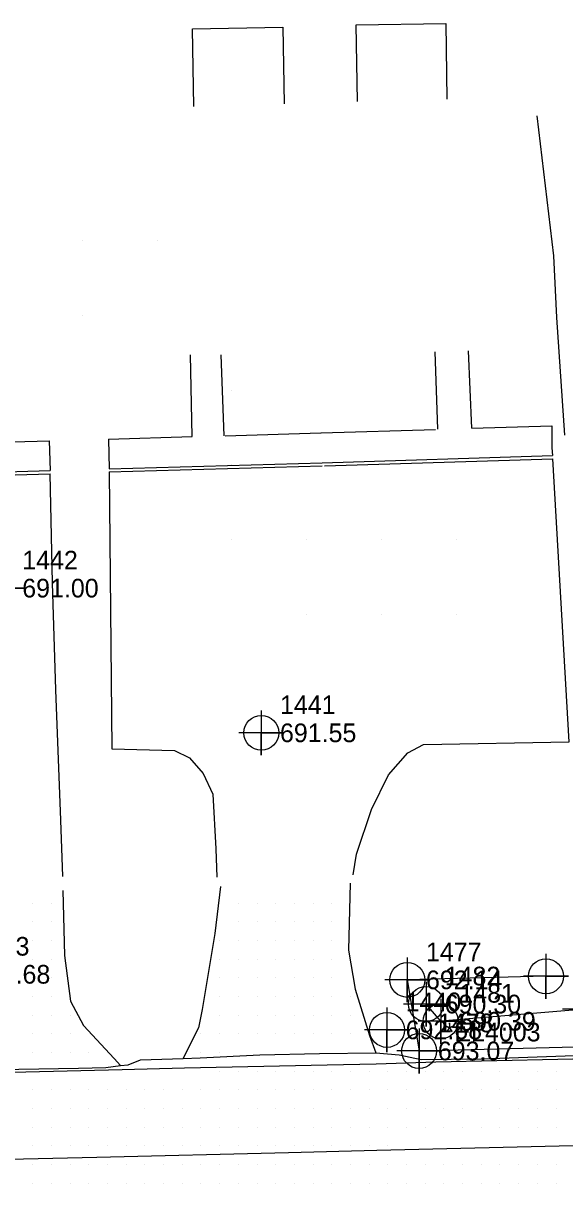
# Model space of a CAD drawing. Extents: x 1755643 to 1760494, y 736519 to 737621.
# Drawn here: x 1758017.5 to 1758089.9, y 736988 to 737144.1 of the extents above; entities that cross this region are included whole.
import ezdxf

# ---------------------------------------------------------------- set-up
doc = ezdxf.new("R2010")
doc.units = 0
for name, color, linetype in [('Exist Horizontal Alignment Curve and Spiral Data', 7, 'Continuous'), ('Exist Railroads Standard Gauge', 7, 'Continuous'), ('Exist Roads EOT', 7, 'Continuous'), ('Old_Level_1', 7, 'Continuous'), ('Old_Level_10', 7, 'Continuous'), ('Old_Level_2', 7, 'Continuous'), ('Old_Level_3', 7, 'Continuous'), ('Prop Corridor Linear Feature', 7, 'Continuous'), ('Prop Dimension', 7, 'Continuous'), ('Prop EOT Dash', 7, 'Continuous'), ('Prop Horizontal Alignment Direction Label', 7, 'Continuous'), ('Prop Lane Lines', 7, 'Continuous'), ('Prop Paint Stripe', 7, 'Continuous'), ('Prop Paved Shoulder', 7, 'Continuous'), ('Scratch_Level_1', 7, 'Continuous'), ('Scratch_Level_2', 7, 'Continuous'), ('Scratch_Level_5', 7, 'Continuous'), ('Scratch_Level_6', 7, 'Continuous'), ('Scratch_Level_9', 7, 'Continuous')]:
    doc.layers.add(name, color=color, linetype=linetype)

msp = doc.modelspace()

# ---------------------------------------------------------------- linework, layer by layer
at = {"layer": 'Exist Horizontal Alignment Curve and Spiral Data'}
for points in [[(1758014.84, 737071.46), (1758014.84, 737065.46), (1758014.84, 737068.46), (1758017.84, 737068.46), (1758011.84, 737068.46)], [(1758049.32, 737052.08), (1758049.32, 737046.08), (1758049.32, 737049.08), (1758052.32, 737049.08), (1758046.32, 737049.08)], [(1758066.13, 737012.29), (1758066.13, 737006.29), (1758066.13, 737009.29), (1758069.13, 737009.29), (1758063.13, 737009.29)]]:
    msp.add_lwpolyline(points, dxfattribs=at)
for centre in [(1758049.32, 737049.08), (1758066.13, 737009.29)]:
    msp.add_circle(centre, 2.34, dxfattribs=at)
at = {"layer": 'Exist Railroads Standard Gauge'}
for p, q in [((1758040.06, 737088.75), (1758039.84, 737099.72)), ((1758043.91, 737099.7), (1758044.31, 737088.88)), ((1758072.95, 737089.74), (1758072.58, 737100.1)), ((1758077.51, 737089.88), (1758077.05, 737100.23)), ((1758057.33, 737089.25), (1758072.61, 737089.73)), ((1758077.51, 737089.88), (1758088.17, 737090.22)), ((1758020.95, 737088.2), (1758021.07, 737084.2)), ((1758028.87, 737088.43), (1758040.06, 737088.75)), ((1758028.87, 737088.43), (1758028.98, 737084.43)), ((1758044.49, 737088.88), (1758057.29, 737089.25)), ((1758028.98, 737084.43), (1758057.46, 737085.25)), ((1758028.99, 737084.02), (1758057.47, 737084.84)), ((1758057.46, 737085.25), (1758088.3, 737086.22)), ((1758057.77, 737084.84), (1758088.31, 737085.8)), ((1758021.41, 737069.17), (1758021.08, 737083.78))]:
    msp.add_line(p, q, dxfattribs=at)
for points in [[(1758062.21, 737133.62), (1758062.03, 737143.91), (1758073.99, 737144.11), (1758074.16, 737133.97)], [(1758040.3, 737132.98), (1758040.12, 737143.36), (1758052.2, 737143.58), (1758052.38, 737133.34)], [(1758086.17, 737131.72), (1758088.43, 737112.98), (1758088.8, 737104.7), (1758089.87, 737088.96)], [(1758088.17, 737090.22), (1758088.2, 737087.24), (1758088.2, 737087.24), (1758088.3, 737086.22)], [(1758009.58, 737087.86), (1758020.95, 737088.2)], [(1758061.63, 737030.06), (1758062.06, 737032.81), (1758064.05, 737038.81), (1758066.35, 737043.44), (1758068.93, 737046.42), (1758071.04, 737047.5), (1758090.51, 737047.87), (1758088.31, 737085.8)], [(1757961.38, 737082.36), (1757991.35, 737083.32), (1758021.07, 737084.2)], [(1757961.39, 737081.94), (1757991.37, 737082.91), (1758021.08, 737083.78)], [(1758028.99, 737084.02), (1758029.34, 737046.94), (1758037.73, 737046.73), (1758039.7, 737045.75), (1758041.55, 737043.64), (1758042.86, 737040.88), (1758043.26, 737033.56), (1758043.36, 737029.73)], [(1758022.78, 737029.85), (1758022.49, 737037.37), (1758021.83, 737054.85), (1758021.41, 737069.17)]]:
    msp.add_lwpolyline(points, dxfattribs=at)
at = {"layer": 'Old_Level_10'}
for points in [[(1758071.36, 737015.75), (1758071.36, 737009.75), (1758071.36, 737012.75), (1758074.36, 737012.75), (1758068.36, 737012.75)], [(1758092.6, 737015.06), (1758092.6, 737009.06), (1758092.6, 737012.06), (1758095.6, 737012.06), (1758089.6, 737012.06)], [(1758073.32, 737013.44), (1758073.32, 737007.44), (1758073.32, 737010.44), (1758076.32, 737010.44), (1758070.32, 737010.44)]]:
    msp.add_lwpolyline(points, dxfattribs=at)
for centre in [(1758071.36, 737012.75), (1758073.32, 737010.44)]:
    msp.add_circle(centre, 2.34, dxfattribs=at)
at = {"layer": 'Prop Corridor Linear Feature'}
for points in [[(1758038.86, 737005.48), (1758041.15, 737005.55), (1758049.14, 737005.94), (1758057.13, 737006.15), (1758064.64, 737006.23)], [(1758000.88, 737003.6), (1758008.88, 737003.81), (1758016.87, 737004.02), (1758024.87, 737004.15), (1758028.53, 737004.27), (1758030.5, 737004.51)]]:
    msp.add_lwpolyline(points, dxfattribs=at)
at = {"layer": 'Prop Dimension'}
msp.add_lwpolyline([(1758092.6, 737012.06), (1758073.32, 737010.44), (1758071.36, 737012.75)], dxfattribs=at)
at = {"layer": 'Prop Lane Lines'}
for points in [[(1758087.4, 737019.47), (1758087.4, 737013.47), (1758087.4, 737016.47), (1758090.4, 737016.47), (1758084.4, 737016.47)], [(1758068.85, 737018.99), (1758068.85, 737012.99), (1758068.85, 737015.99), (1758071.85, 737015.99), (1758065.85, 737015.99)], [(1758070.44, 737009.47), (1758070.44, 737003.47), (1758070.44, 737006.47), (1758073.44, 737006.47), (1758067.44, 737006.47)]]:
    msp.add_lwpolyline(points, dxfattribs=at)
for centre in [(1758068.85, 737015.99), (1758087.4, 737016.47), (1758070.44, 737006.47)]:
    msp.add_circle(centre, 2.34, dxfattribs=at)
at = {"layer": 'Prop Paint Stripe'}
for p, q in [((1758025.4, 737115), (1758025.4, 737115)), ((1758035.4, 737115), (1758035.4, 737115)), ((1758025.4, 737105), (1758025.4, 737105)), ((1758045.4, 737094.99), (1758045.4, 737094.99)), ((1758045.4, 737084.99), (1758045.4, 737084.99)), ((1758045.4, 737074.99), (1758045.4, 737074.99)), ((1758055.4, 737074.99), (1758055.4, 737074.99)), ((1758065.4, 737074.99), (1758065.4, 737074.99)), ((1758075.4, 737074.99), (1758075.4, 737074.99)), ((1758055.4, 737064.99), (1758055.4, 737064.99)), ((1758065.4, 737064.99), (1758065.4, 737064.99)), ((1758075.4, 737064.99), (1758075.4, 737064.99))]:
    msp.add_line(p, q, dxfattribs=at)
at = {"layer": 'Scratch_Level_1'}
for points in [[(1758064.64, 737006.23), (1758067.75, 737005.95), (1758070.73, 737005.31), (1758078.73, 737005.43), (1758093.71, 737005.95), (1758108.69, 737006.38), (1758123.68, 737006.69), (1758138.67, 737007.07), (1758153.65, 737007.78), (1758168.64, 737008.2), (1758183.63, 737008.63), (1758188.93, 737008.88)], [(1758030.5, 737004.51), (1758031.53, 737004.63), (1758033.15, 737005.3), (1758038.86, 737005.48)]]:
    msp.add_lwpolyline(points, dxfattribs=at)
at = {"layer": 'Scratch_Level_2'}
for p, q in [((1758018.75, 737026.25), (1758018.75, 737026.25)), ((1758021.25, 737026.25), (1758021.25, 737026.25)), ((1758046.25, 737026.25), (1758046.25, 737026.25)), ((1758048.75, 737026.25), (1758048.75, 737026.25)), ((1758051.25, 737026.25), (1758051.25, 737026.25)), ((1758053.75, 737026.25), (1758053.75, 737026.25)), ((1758056.25, 737026.25), (1758056.25, 737026.25)), ((1758058.75, 737026.25), (1758058.75, 737026.25)), ((1758018.75, 737023.75), (1758018.75, 737023.75)), ((1758021.25, 737023.75), (1758021.25, 737023.75)), ((1758046.25, 737023.75), (1758046.25, 737023.75)), ((1758048.75, 737023.75), (1758048.75, 737023.75)), ((1758051.25, 737023.75), (1758051.25, 737023.75)), ((1758053.75, 737023.75), (1758053.75, 737023.75)), ((1758056.25, 737023.75), (1758056.25, 737023.75)), ((1758058.75, 737023.75), (1758058.75, 737023.75)), ((1758018.75, 737021.25), (1758018.75, 737021.25)), ((1758021.25, 737021.25), (1758021.25, 737021.25)), ((1758043.75, 737021.25), (1758043.75, 737021.25)), ((1758046.25, 737021.25), (1758046.25, 737021.25)), ((1758048.75, 737021.25), (1758048.75, 737021.25)), ((1758051.25, 737021.25), (1758051.25, 737021.25)), ((1758053.75, 737021.25), (1758053.75, 737021.25)), ((1758056.25, 737021.25), (1758056.25, 737021.25)), ((1758058.75, 737021.25), (1758058.75, 737021.25)), ((1758018.75, 737018.75), (1758018.75, 737018.75)), ((1758021.25, 737018.75), (1758021.25, 737018.75)), ((1758043.75, 737018.75), (1758043.75, 737018.75)), ((1758046.25, 737018.75), (1758046.25, 737018.75)), ((1758048.75, 737018.75), (1758048.75, 737018.75)), ((1758051.25, 737018.75), (1758051.25, 737018.75)), ((1758053.75, 737018.75), (1758053.75, 737018.75)), ((1758056.25, 737018.75), (1758056.25, 737018.75)), ((1758058.75, 737018.75), (1758058.75, 737018.75)), ((1758018.75, 737016.25), (1758018.75, 737016.25)), ((1758021.25, 737016.25), (1758021.25, 737016.25)), ((1758043.75, 737016.25), (1758043.75, 737016.25)), ((1758046.25, 737016.25), (1758046.25, 737016.25)), ((1758048.75, 737016.25), (1758048.75, 737016.25)), ((1758051.25, 737016.25), (1758051.25, 737016.25)), ((1758053.75, 737016.25), (1758053.75, 737016.25)), ((1758056.25, 737016.25), (1758056.25, 737016.25)), ((1758058.75, 737016.25), (1758058.75, 737016.25)), ((1758018.75, 737013.75), (1758018.75, 737013.75)), ((1758021.25, 737013.75), (1758021.25, 737013.75)), ((1758043.75, 737013.75), (1758043.75, 737013.75)), ((1758046.25, 737013.75), (1758046.25, 737013.75)), ((1758048.75, 737013.75), (1758048.75, 737013.75)), ((1758051.25, 737013.75), (1758051.25, 737013.75)), ((1758053.75, 737013.75), (1758053.75, 737013.75)), ((1758056.25, 737013.75), (1758056.25, 737013.75)), ((1758058.75, 737013.75), (1758058.75, 737013.75)), ((1758061.25, 737013.75), (1758061.25, 737013.75)), ((1758018.75, 737011.25), (1758018.75, 737011.25)), ((1758021.25, 737011.25), (1758021.25, 737011.25)), ((1758023.75, 737011.25), (1758023.75, 737011.25)), ((1758043.75, 737011.25), (1758043.75, 737011.25)), ((1758046.25, 737011.25), (1758046.25, 737011.25)), ((1758048.75, 737011.25), (1758048.75, 737011.25)), ((1758051.25, 737011.25), (1758051.25, 737011.25)), ((1758053.75, 737011.25), (1758053.75, 737011.25)), ((1758056.25, 737011.25), (1758056.25, 737011.25)), ((1758058.75, 737011.25), (1758058.75, 737011.25)), ((1758061.25, 737011.25), (1758061.25, 737011.25)), ((1758018.75, 737008.75), (1758018.75, 737008.75)), ((1758021.25, 737008.75), (1758021.25, 737008.75)), ((1758023.75, 737008.75), (1758023.75, 737008.75)), ((1758041.25, 737008.75), (1758041.25, 737008.75)), ((1758043.75, 737008.75), (1758043.75, 737008.75)), ((1758046.25, 737008.75), (1758046.25, 737008.75)), ((1758048.75, 737008.75), (1758048.75, 737008.75)), ((1758051.25, 737008.75), (1758051.25, 737008.75)), ((1758053.75, 737008.75), (1758053.75, 737008.75)), ((1758056.25, 737008.75), (1758056.25, 737008.75)), ((1758058.75, 737008.75), (1758058.75, 737008.75)), ((1758061.25, 737008.75), (1758061.25, 737008.75)), ((1758018.75, 737006.25), (1758018.75, 737006.25)), ((1758021.25, 737006.25), (1758021.25, 737006.25)), ((1758023.75, 737006.25), (1758023.75, 737006.25)), ((1758026.25, 737006.25), (1758026.25, 737006.25)), ((1758041.25, 737006.25), (1758041.25, 737006.25)), ((1758043.75, 737006.25), (1758043.75, 737006.25)), ((1758043.75, 737003.75), (1758043.75, 737003.75)), ((1758046.25, 737003.75), (1758046.25, 737003.75)), ((1758048.75, 737003.75), (1758048.75, 737003.75)), ((1758051.25, 737003.75), (1758051.25, 737003.75)), ((1758053.75, 737003.75), (1758053.75, 737003.75)), ((1758056.25, 737003.75), (1758056.25, 737003.75)), ((1758058.75, 737003.75), (1758058.75, 737003.75)), ((1758061.25, 737003.75), (1758061.25, 737003.75)), ((1758063.75, 737003.75), (1758063.75, 737003.75)), ((1758066.25, 737003.75), (1758066.25, 737003.75)), ((1758068.75, 737003.75), (1758068.75, 737003.75)), ((1758071.25, 737003.75), (1758071.25, 737003.75)), ((1758073.75, 737003.75), (1758073.75, 737003.75)), ((1758076.25, 737003.75), (1758076.25, 737003.75)), ((1758078.75, 737003.75), (1758078.75, 737003.75)), ((1758081.25, 737003.75), (1758081.25, 737003.75)), ((1758083.75, 737003.75), (1758083.75, 737003.75)), ((1758086.25, 737003.75), (1758086.25, 737003.75)), ((1758088.75, 737003.75), (1758088.75, 737003.75)), ((1758018.75, 737001.25), (1758018.75, 737001.25)), ((1758021.25, 737001.25), (1758021.25, 737001.25)), ((1758023.75, 737001.25), (1758023.75, 737001.25)), ((1758026.25, 737001.25), (1758026.25, 737001.25)), ((1758028.75, 737001.25), (1758028.75, 737001.25)), ((1758031.25, 737001.25), (1758031.25, 737001.25)), ((1758033.75, 737001.25), (1758033.75, 737001.25)), ((1758036.25, 737001.25), (1758036.25, 737001.25)), ((1758038.75, 737001.25), (1758038.75, 737001.25)), ((1758041.25, 737001.25), (1758041.25, 737001.25)), ((1758043.75, 737001.25), (1758043.75, 737001.25)), ((1758046.25, 737001.25), (1758046.25, 737001.25)), ((1758048.75, 737001.25), (1758048.75, 737001.25)), ((1758051.25, 737001.25), (1758051.25, 737001.25)), ((1758053.75, 737001.25), (1758053.75, 737001.25)), ((1758056.25, 737001.25), (1758056.25, 737001.25)), ((1758058.75, 737001.25), (1758058.75, 737001.25)), ((1758061.25, 737001.25), (1758061.25, 737001.25)), ((1758063.75, 737001.25), (1758063.75, 737001.25)), ((1758066.25, 737001.25), (1758066.25, 737001.25)), ((1758068.75, 737001.25), (1758068.75, 737001.25)), ((1758071.25, 737001.25), (1758071.25, 737001.25)), ((1758073.75, 737001.25), (1758073.75, 737001.25)), ((1758076.25, 737001.25), (1758076.25, 737001.25)), ((1758078.75, 737001.25), (1758078.75, 737001.25)), ((1758081.25, 737001.25), (1758081.25, 737001.25)), ((1758083.75, 737001.25), (1758083.75, 737001.25)), ((1758086.25, 737001.25), (1758086.25, 737001.25)), ((1758088.75, 737001.25), (1758088.75, 737001.25)), ((1758018.75, 736998.75), (1758018.75, 736998.75)), ((1758021.25, 736998.75), (1758021.25, 736998.75)), ((1758023.75, 736998.75), (1758023.75, 736998.75)), ((1758026.25, 736998.75), (1758026.25, 736998.75)), ((1758028.75, 736998.75), (1758028.75, 736998.75)), ((1758031.25, 736998.75), (1758031.25, 736998.75)), ((1758033.75, 736998.75), (1758033.75, 736998.75)), ((1758036.25, 736998.75), (1758036.25, 736998.75)), ((1758038.75, 736998.75), (1758038.75, 736998.75)), ((1758041.25, 736998.75), (1758041.25, 736998.75)), ((1758043.75, 736998.75), (1758043.75, 736998.75)), ((1758046.25, 736998.75), (1758046.25, 736998.75)), ((1758048.75, 736998.75), (1758048.75, 736998.75)), ((1758051.25, 736998.75), (1758051.25, 736998.75)), ((1758053.75, 736998.75), (1758053.75, 736998.75)), ((1758056.25, 736998.75), (1758056.25, 736998.75)), ((1758058.75, 736998.75), (1758058.75, 736998.75)), ((1758061.25, 736998.75), (1758061.25, 736998.75)), ((1758063.75, 736998.75), (1758063.75, 736998.75)), ((1758066.25, 736998.75), (1758066.25, 736998.75)), ((1758068.75, 736998.75), (1758068.75, 736998.75)), ((1758071.25, 736998.75), (1758071.25, 736998.75)), ((1758073.75, 736998.75), (1758073.75, 736998.75)), ((1758076.25, 736998.75), (1758076.25, 736998.75)), ((1758078.75, 736998.75), (1758078.75, 736998.75)), ((1758081.25, 736998.75), (1758081.25, 736998.75)), ((1758083.75, 736998.75), (1758083.75, 736998.75)), ((1758086.25, 736998.75), (1758086.25, 736998.75)), ((1758088.75, 736998.75), (1758088.75, 736998.75)), ((1758018.75, 736996.25), (1758018.75, 736996.25)), ((1758021.25, 736996.25), (1758021.25, 736996.25)), ((1758023.75, 736996.25), (1758023.75, 736996.25)), ((1758026.25, 736996.25), (1758026.25, 736996.25)), ((1758028.75, 736996.25), (1758028.75, 736996.25)), ((1758031.25, 736996.25), (1758031.25, 736996.25)), ((1758033.75, 736996.25), (1758033.75, 736996.25)), ((1758036.25, 736996.25), (1758036.25, 736996.25)), ((1758038.75, 736996.25), (1758038.75, 736996.25)), ((1758041.25, 736996.25), (1758041.25, 736996.25)), ((1758043.75, 736996.25), (1758043.75, 736996.25)), ((1758046.25, 736996.25), (1758046.25, 736996.25)), ((1758048.75, 736996.25), (1758048.75, 736996.25)), ((1758051.25, 736996.25), (1758051.25, 736996.25)), ((1758053.75, 736996.25), (1758053.75, 736996.25)), ((1758056.25, 736996.25), (1758056.25, 736996.25)), ((1758058.75, 736996.25), (1758058.75, 736996.25)), ((1758061.25, 736996.25), (1758061.25, 736996.25)), ((1758063.75, 736996.25), (1758063.75, 736996.25)), ((1758066.25, 736996.25), (1758066.25, 736996.25)), ((1758068.75, 736996.25), (1758068.75, 736996.25)), ((1758071.25, 736996.25), (1758071.25, 736996.25)), ((1758073.75, 736996.25), (1758073.75, 736996.25)), ((1758076.25, 736996.25), (1758076.25, 736996.25)), ((1758078.75, 736996.25), (1758078.75, 736996.25)), ((1758081.25, 736996.25), (1758081.25, 736996.25)), ((1758083.75, 736996.25), (1758083.75, 736996.25)), ((1758086.25, 736996.25), (1758086.25, 736996.25)), ((1758088.75, 736996.25), (1758088.75, 736996.25)), ((1758018.75, 736993.75), (1758018.75, 736993.75)), ((1758021.25, 736993.75), (1758021.25, 736993.75)), ((1758023.75, 736993.75), (1758023.75, 736993.75)), ((1758026.25, 736993.75), (1758026.25, 736993.75)), ((1758028.75, 736993.75), (1758028.75, 736993.75)), ((1758031.25, 736993.75), (1758031.25, 736993.75)), ((1758033.75, 736993.75), (1758033.75, 736993.75)), ((1758036.25, 736993.75), (1758036.25, 736993.75)), ((1758038.75, 736993.75), (1758038.75, 736993.75)), ((1758041.25, 736993.75), (1758041.25, 736993.75)), ((1758043.75, 736993.75), (1758043.75, 736993.75)), ((1758046.25, 736993.75), (1758046.25, 736993.75)), ((1758048.75, 736993.75), (1758048.75, 736993.75)), ((1758051.25, 736993.75), (1758051.25, 736993.75)), ((1758053.75, 736993.75), (1758053.75, 736993.75)), ((1758056.25, 736993.75), (1758056.25, 736993.75)), ((1758058.75, 736993.75), (1758058.75, 736993.75)), ((1758061.25, 736993.75), (1758061.25, 736993.75)), ((1758063.75, 736993.75), (1758063.75, 736993.75)), ((1758066.25, 736993.75), (1758066.25, 736993.75)), ((1758018.75, 736991.25), (1758018.75, 736991.25)), ((1758021.25, 736991.25), (1758021.25, 736991.25)), ((1758023.75, 736991.25), (1758023.75, 736991.25)), ((1758026.25, 736991.25), (1758026.25, 736991.25)), ((1758028.75, 736991.25), (1758028.75, 736991.25)), ((1758031.25, 736991.25), (1758031.25, 736991.25)), ((1758033.75, 736991.25), (1758033.75, 736991.25)), ((1758036.25, 736991.25), (1758036.25, 736991.25)), ((1758038.75, 736991.25), (1758038.75, 736991.25)), ((1758041.25, 736991.25), (1758041.25, 736991.25)), ((1758043.75, 736991.25), (1758043.75, 736991.25)), ((1758046.25, 736991.25), (1758046.25, 736991.25)), ((1758048.75, 736991.25), (1758048.75, 736991.25)), ((1758051.25, 736991.25), (1758051.25, 736991.25)), ((1758053.75, 736991.25), (1758053.75, 736991.25)), ((1758056.25, 736991.25), (1758056.25, 736991.25)), ((1758058.75, 736991.25), (1758058.75, 736991.25)), ((1758061.25, 736991.25), (1758061.25, 736991.25)), ((1758063.75, 736991.25), (1758063.75, 736991.25)), ((1758066.25, 736991.25), (1758066.25, 736991.25)), ((1758068.75, 736991.25), (1758068.75, 736991.25)), ((1758071.25, 736991.25), (1758071.25, 736991.25)), ((1758073.75, 736991.25), (1758073.75, 736991.25)), ((1758076.25, 736991.25), (1758076.25, 736991.25)), ((1758078.75, 736991.25), (1758078.75, 736991.25)), ((1758081.25, 736991.25), (1758081.25, 736991.25)), ((1758083.75, 736991.25), (1758083.75, 736991.25)), ((1758086.25, 736991.25), (1758086.25, 736991.25)), ((1758088.75, 736991.25), (1758088.75, 736991.25)), ((1758018.75, 736988.75), (1758018.75, 736988.75)), ((1758021.25, 736988.75), (1758021.25, 736988.75)), ((1758023.75, 736988.75), (1758023.75, 736988.75)), ((1758026.25, 736988.75), (1758026.25, 736988.75)), ((1758028.75, 736988.75), (1758028.75, 736988.75)), ((1758031.25, 736988.75), (1758031.25, 736988.75)), ((1758033.75, 736988.75), (1758033.75, 736988.75)), ((1758036.25, 736988.75), (1758036.25, 736988.75)), ((1758038.75, 736988.75), (1758038.75, 736988.75)), ((1758041.25, 736988.75), (1758041.25, 736988.75)), ((1758043.75, 736988.75), (1758043.75, 736988.75)), ((1758046.25, 736988.75), (1758046.25, 736988.75)), ((1758048.75, 736988.75), (1758048.75, 736988.75)), ((1758051.25, 736988.75), (1758051.25, 736988.75)), ((1758053.75, 736988.75), (1758053.75, 736988.75)), ((1758056.25, 736988.75), (1758056.25, 736988.75)), ((1758058.75, 736988.75), (1758058.75, 736988.75)), ((1758061.25, 736988.75), (1758061.25, 736988.75)), ((1758063.75, 736988.75), (1758063.75, 736988.75)), ((1758066.25, 736988.75), (1758066.25, 736988.75)), ((1758068.75, 736988.75), (1758068.75, 736988.75)), ((1758071.25, 736988.75), (1758071.25, 736988.75)), ((1758073.75, 736988.75), (1758073.75, 736988.75)), ((1758076.25, 736988.75), (1758076.25, 736988.75)), ((1758078.75, 736988.75), (1758078.75, 736988.75)), ((1758081.25, 736988.75), (1758081.25, 736988.75)), ((1758083.75, 736988.75), (1758083.75, 736988.75)), ((1758086.25, 736988.75), (1758086.25, 736988.75)), ((1758088.75, 736988.75), (1758088.75, 736988.75))]:
    msp.add_line(p, q, dxfattribs=at)
at = {"layer": 'Scratch_Level_5'}
for points in [[(1758064.69, 737004.75), (1758072.66, 737005.01), (1758089, 737005.36), (1758105.09, 737005.72), (1758122.29, 737006.14), (1758136.53, 737006.53), (1758157.9, 737007.11), (1758173.26, 737007.48), (1758191.67, 737007.95), (1758209.14, 737008.37), (1758232.19, 737008.9), (1758248.18, 737009.28), (1758264.32, 737009.73)], [(1757864.46, 736999.5), (1757881.5, 736999.9), (1757895.35, 737000.32), (1757902.81, 737000.52), (1757928.43, 737001.25), (1757948.52, 737001.83), (1757969.15, 737002.41), (1757999.38, 737003.24), (1758030.72, 737004), (1758039.05, 737004.19), (1758058.14, 737004.63), (1758064.69, 737004.75)], [(1758064.8, 736993.19), (1758092.92, 736993.85), (1758127.56, 736994.73), (1758149.64, 736995.32), (1758184.39, 736996.19), (1758213.94, 736996.95), (1758233.95, 736997.45), (1758251.62, 736997.88), (1758264.67, 736998.25)], [(1757864.9, 736988.02), (1757894.4, 736988.77), (1757921.62, 736989.52), (1757947.43, 736990.24), (1757966.33, 736990.77), (1757986.39, 736991.26), (1757996.91, 736991.5), (1758005.69, 736991.75), (1758027.31, 736992.26), (1758052.98, 736992.87), (1758064.8, 736993.19)]]:
    msp.add_lwpolyline(points, dxfattribs=at)
at = {"layer": 'Scratch_Level_6'}
for points in [[(1758061.21, 737028.95), (1758060.97, 737019.99), (1758061.87, 737014.76), (1758063.81, 737008.55), (1758064.64, 737006.23)], [(1758022.78, 737027.95), (1758022.99, 737019.27), (1758023.79, 737013.15), (1758025.55, 737009.86), (1758029.65, 737005.45), (1758030.5, 737004.51)], [(1758043.88, 737028.49), (1758043.12, 737022.19), (1758041.39, 737012.01), (1758040.91, 737009.56), (1758038.99, 737005.75), (1758038.86, 737005.48)]]:
    msp.add_lwpolyline(points, dxfattribs=at)
at = {"layer": 'Scratch_Level_9'}
msp.add_lwpolyline([(1758087.4, 737016.47), (1758068.85, 737015.99), (1758070.44, 737006.47), (1758093.05, 737007.08)], dxfattribs=at)

# ---------------------------------------------------------------- texts
at = {"layer": 'Exist Roads EOT'}
for s, p in [('1442', (1758017.34, 737070.96)), ('1441', (1758051.82, 737051.58)), ('1440', (1758068.63, 737011.79))]:
    msp.add_text(s, height=2.5, dxfattribs=at).set_placement(p)
at = {"layer": 'Old_Level_1'}
for s, p in [('1482', (1758073.86, 737015.25)), ('1481', (1758075.82, 737012.94))]:
    msp.add_text(s, height=2.5, dxfattribs=at).set_placement(p)
at = {"layer": 'Old_Level_2'}
for s, p in [('690.30', (1758073.86, 737011.5)), ('690.39', (1758075.82, 737009.19))]:
    msp.add_text(s, height=2.5, dxfattribs=at).set_placement(p)
at = {"layer": 'Old_Level_3'}
for s, p in [('690.68', (1758010.87, 737015.49)), ('692.14', (1758071.35, 737014.74)), ('693.07', (1758072.94, 737005.22))]:
    msp.add_text(s, height=2.5, dxfattribs=at).set_placement(p)
at = {"layer": 'Prop EOT Dash'}
for s, p in [('1453', (1758010.87, 737019.24)), ('1477', (1758071.35, 737018.49)), ('1478', (1758072.94, 737008.97))]:
    msp.add_text(s, height=2.5, dxfattribs=at).set_placement(p)
at = {"layer": 'Prop Horizontal Alignment Direction Label'}
msp.add_text('*EL4003', height=2.5, dxfattribs=at).set_placement((1758073.86, 737007.75))
at = {"layer": 'Prop Paved Shoulder'}
for s, p in [('691.00', (1758017.34, 737067.21)), ('691.55', (1758051.82, 737047.83)), ('692.68', (1758068.63, 737008.04))]:
    msp.add_text(s, height=2.5, dxfattribs=at).set_placement(p)

doc.saveas('drawing.dxf')
